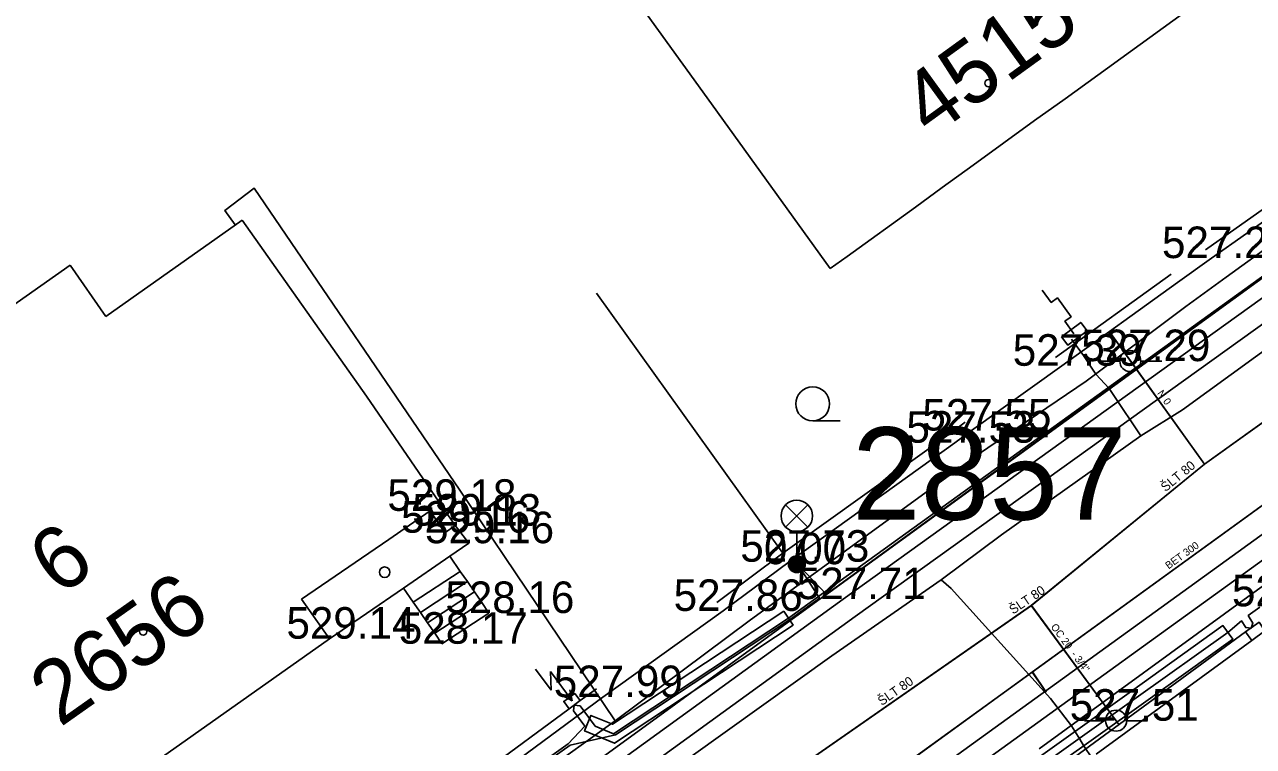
# Model space of a CAD drawing. Extents: x -668867 to -667827, y -1131943 to -1131019.
# Drawn here: x -668691.62 to -668662.4, y -1131354.94 to -1131337.78 of the extents above; entities that cross this region are included whole.
import ezdxf

# ---------------------------------------------------------------- set-up
doc = ezdxf.new("R2010")
doc.units = 0
for name, color, linetype in [('G_Bod_tecka', 7, 'Continuous'), ('G_Bod_vyska', 7, 'Continuous'), ('G_Budovy-znacky', 7, 'Continuous'), ('G_Budovy_Objekty', 7, 'Continuous'), ('G_Budovy_vstupy', 7, 'Continuous'), ('G_Cesty_Schody', 7, 'Continuous'), ('G_Cisla_orientacni', 7, 'Continuous'), ('G_Cisla_popisna', 7, 'Continuous'), ('G_Objekty_technicke', 7, 'Continuous'), ('G_Plochy_zpevnene', 7, 'Continuous'), ('G_Ploty', 7, 'Continuous'), ('G_Ploty_vstupy', 7, 'Continuous'), ('G_Site-Rozvadece', 7, 'Continuous'), ('G_Site-vodovod', 7, 'Continuous'), ('G_Z_CHRANICKA-TEPLOVOD_kotovane', 7, 'Continuous'), ('G_Z_ELsilove_podz_kotovane', 7, 'Continuous'), ('G_Z_KANAL_podz_kotovane', 7, 'Continuous'), ('G_Z_PLYNY_podz_geodeticky', 7, 'Continuous'), ('G_Z_SPOJE_podz_geodeticky', 7, 'Continuous'), ('G_Z_SPOJE_podz_kotovane', 7, 'Continuous'), ('G_Z_SPOJE_podz_priblizne', 7, 'Continuous'), ('G_Z_VODA_podz_kotovane', 7, 'Continuous'), ('G_Zelen-Znacky', 7, 'Continuous'), ('Vrstva 1', 7, 'Continuous'), ('Vrstva 10', 7, 'Continuous'), ('Vrstva 13', 7, 'Continuous'), ('Vrstva 17', 7, 'Continuous'), ('Vrstva 26', 7, 'Continuous'), ('Vrstva 3', 7, 'Continuous'), ('Vrstva 4', 7, 'Continuous'), ('Vrstva 6', 7, 'Continuous')]:
    doc.layers.add(name, color=color, linetype=linetype)

msp = doc.modelspace()

# ---------------------------------------------------------------- linework, layer by layer
at = {"layer": 'G_Bod_tecka'}
for p, q in [((-668663.4, -1131343.33), (-668663.4, -1131343.33)), ((-668666.96, -1131345.89), (-668666.96, -1131345.89)), ((-668665.33, -1131345.78), (-668665.33, -1131345.78)), ((-668669.11, -1131347.43), (-668669.11, -1131347.43)), ((-668669.5, -1131347.72), (-668669.5, -1131347.72)), ((-668681.98, -1131349.34), (-668681.98, -1131349.34)), ((-668681.38, -1131349.69), (-668681.38, -1131349.69)), ((-668681.63, -1131349.86), (-668681.63, -1131349.86)), ((-668681.06, -1131350.11), (-668681.06, -1131350.11)), ((-668673.44, -1131350.55), (-668673.44, -1131350.55)), ((-668673.26, -1131350.61), (-668673.26, -1131350.61)), ((-668672.16, -1131351.44), (-668672.16, -1131351.44)), ((-668680.58, -1131351.77), (-668680.58, -1131351.77)), ((-668675.01, -1131351.72), (-668675.01, -1131351.72)), ((-668684.37, -1131352.38), (-668684.37, -1131352.38)), ((-668681.7, -1131352.5), (-668681.7, -1131352.5)), ((-668677.87, -1131353.77), (-668677.87, -1131353.77)), ((-668665.67, -1131354.33), (-668665.67, -1131354.33))]:
    msp.add_line(p, q, dxfattribs=at)
at = {"layer": 'G_Budovy-znacky'}
for centre, radius in [((-668668.7, -1131339.17), 0.0875), ((-668683.06, -1131350.8), 0.125), ((-668688.8, -1131352.21), 0.0875)]:
    msp.add_circle(centre, radius, dxfattribs=at)
at = {"layer": 'G_Budovy_Objekty'}
for p, q in [((-668675.39, -1131339.52), (-668678.46, -1131335.27)), ((-668666.88, -1131339.54), (-668663.54, -1131337.12)), ((-668675.39, -1131339.52), (-668672.47, -1131343.58)), ((-668669.07, -1131341.12), (-668667.61, -1131340.06)), ((-668670.44, -1131342.12), (-668669.8, -1131341.65)), ((-668689.69, -1131344.72), (-668686.45, -1131342.43)), ((-668683.49, -1131346.61), (-668686.45, -1131342.43)), ((-668672.47, -1131343.58), (-668672.06, -1131343.29)), ((-668692.92, -1131345.17), (-668690.54, -1131343.5)), ((-668690.54, -1131343.5), (-668689.69, -1131344.72)), ((-668683.49, -1131346.61), (-668681.38, -1131349.69)), ((-668681.63, -1131349.86), (-668681.98, -1131349.34)), ((-668681.38, -1131349.69), (-668681.63, -1131349.86)), ((-668681.06, -1131350.11), (-668681.38, -1131349.69)), ((-668682.96, -1131350.02), (-668685.04, -1131351.44)), ((-668681.51, -1131350.42), (-668681.06, -1131350.11)), ((-668682.61, -1131351.18), (-668681.51, -1131350.42)), ((-668684.37, -1131352.38), (-668682.61, -1131351.18)), ((-668685.04, -1131351.44), (-668684.37, -1131352.38)), ((-668692.65, -1131358.23), (-668684.37, -1131352.38))]:
    msp.add_line(p, q, dxfattribs=at)
at = {"layer": 'G_Budovy_vstupy'}
msp.add_line((-668682.96, -1131350.02), (-668681.98, -1131349.34), dxfattribs=at)
msp.add_lwpolyline([(-668672.06, -1131343.29), (-668670.44, -1131342.12)], dxfattribs=at)
at = {"layer": 'G_Cesty_Schody'}
for p, q in [((-668646.06, -1131338.24), (-668670.62, -1131355.99)), ((-668655.32, -1131339.96), (-668671.87, -1131351.85)), ((-668681.26, -1131350.78), (-668681.51, -1131350.42)), ((-668682.38, -1131351.51), (-668681.26, -1131350.78)), ((-668681.09, -1131351.02), (-668681.26, -1131350.78)), ((-668682.38, -1131351.51), (-668682.61, -1131351.18)), ((-668682.21, -1131351.76), (-668681.09, -1131351.02)), ((-668682.04, -1131352), (-668680.92, -1131351.27)), ((-668680.92, -1131351.27), (-668681.09, -1131351.02)), ((-668680.75, -1131351.52), (-668680.92, -1131351.27)), ((-668682.21, -1131351.76), (-668682.38, -1131351.51)), ((-668681.87, -1131352.25), (-668680.75, -1131351.52)), ((-668680.58, -1131351.77), (-668680.75, -1131351.52)), ((-668671.87, -1131351.85), (-668715.28, -1131383.29)), ((-668682.04, -1131352), (-668682.21, -1131351.76)), ((-668681.7, -1131352.5), (-668680.58, -1131351.77)), ((-668681.87, -1131352.25), (-668682.04, -1131352)), ((-668681.7, -1131352.5), (-668681.87, -1131352.25))]:
    msp.add_line(p, q, dxfattribs=at)
at = {"layer": 'G_Objekty_technicke'}
for p, q in [((-668673.525, -1131349.195), (-668672.995, -1131349.725)), ((-668673.525, -1131349.725), (-668672.995, -1131349.195)), ((-668673.26, -1131350.61), (-668673.26, -1131349.835))]:
    msp.add_line(p, q, dxfattribs=at)
for centre, radius in [((-668673.26, -1131349.46), 0.375), ((-668673.26, -1131350.61), 0.2), ((-668673.26, -1131350.61), 0.18), ((-668673.26, -1131350.61), 0.16), ((-668673.26, -1131350.61), 0.14), ((-668673.26, -1131350.61), 0.12), ((-668673.26, -1131350.61), 0.1), ((-668673.26, -1131350.61), 0.08), ((-668673.26, -1131350.61), 0.06), ((-668673.26, -1131350.61), 0.04), ((-668673.26, -1131350.61), 0.02)]:
    msp.add_circle(centre, radius, dxfattribs=at)
at = {"layer": 'G_Plochy_zpevnene'}
for p, q in [((-668645.76, -1131338.64), (-668670.33, -1131356.39)), ((-668655.68, -1131339.6), (-668672.16, -1131351.44)), ((-668672.16, -1131351.44), (-668715.57, -1131382.88))]:
    msp.add_line(p, q, dxfattribs=at)
at = {"layer": 'G_Ploty'}
for p, q in [((-668659.96, -1131340.6), (-668663.54, -1131343.13)), ((-668659.82, -1131340.8), (-668663.4, -1131343.33)), ((-668664.36, -1131343.71), (-668667.11, -1131345.69)), ((-668666.96, -1131345.89), (-668664.21, -1131343.91)), ((-668678.02, -1131344.16), (-668673.59, -1131350.35)), ((-668669.64, -1131347.52), (-668669.26, -1131347.23)), ((-668669.5, -1131347.72), (-668669.11, -1131347.43)), ((-668669.64, -1131347.52), (-668673.59, -1131350.35)), ((-668673.44, -1131350.55), (-668669.5, -1131347.72)), ((-668673.59, -1131350.35), (-668675.16, -1131351.52)), ((-668675.01, -1131351.72), (-668673.44, -1131350.55)), ((-668672.43, -1131359.42), (-668662.59, -1131352.22)), ((-668666.14, -1131355.13), (-668662.44, -1131352.42)), ((-668678.02, -1131353.57), (-668678.41, -1131353.85)), ((-668677.87, -1131353.77), (-668680.54, -1131355.74)), ((-668678.67, -1131354.05), (-668680.69, -1131355.54))]:
    msp.add_line(p, q, dxfattribs=at)
at = {"layer": 'G_Ploty_vstupy'}
for p, q in [((-668664.21, -1131343.91), (-668663.4, -1131343.33)), ((-668669.11, -1131347.43), (-668666.96, -1131345.89)), ((-668677.87, -1131353.77), (-668675.01, -1131351.72))]:
    msp.add_line(p, q, dxfattribs=at)
for points in [[(-668667.61, -1131340.06), (-668666.88, -1131339.54)], [(-668669.8, -1131341.65), (-668669.07, -1131341.12)]]:
    msp.add_lwpolyline(points, dxfattribs=at)
at = {"layer": 'G_Site-Rozvadece'}
for p, q in [((-668679.47, -1131353.103), (-668679.098, -1131353.607)), ((-668679.098, -1131353.607), (-668679.12, -1131353.157)), ((-668679.12, -1131353.157), (-668678.6, -1131353.86)), ((-668678.6, -1131353.86), (-668678.657, -1131353.598)), ((-668678.834, -1131353.729), (-668678.6, -1131353.86))]:
    msp.add_line(p, q, dxfattribs=at)
for points in [[(-668666.67, -1131345.13), (-668666.886, -1131344.832), (-668666.738, -1131344.724), (-668667.063, -1131344.278), (-668667.211, -1131344.385), (-668667.429, -1131344.089)], [(-668666.97, -1131345.2), (-668666.51, -1131344.86), (-668666.36, -1131345.06), (-668666.82, -1131345.4), (-668666.97, -1131345.2)]]:
    msp.add_lwpolyline(points, dxfattribs=at)
for points in [[(-668662.59, -1131352.22), (-668662.44, -1131352.42), (-668662.13, -1131352.19), (-668662.27, -1131351.99)], [(-668678.67, -1131354.05), (-668678.41, -1131353.85), (-668678.54, -1131353.68), (-668678.8, -1131353.87)]]:
    msp.add_lwpolyline(points, close=True, dxfattribs=at)
at = {"layer": 'G_Site-vodovod'}
for p, q in [((-668665.58, -1131345.78), (-668666.08, -1131345.78)), ((-668665.08, -1131345.78), (-668664.58, -1131345.78)), ((-668665.92, -1131354.33), (-668666.42, -1131354.33)), ((-668665.42, -1131354.33), (-668664.92, -1131354.33))]:
    msp.add_line(p, q, dxfattribs=at)
for centre in [(-668665.33, -1131345.78), (-668665.67, -1131354.33)]:
    msp.add_circle(centre, 0.25, dxfattribs=at)
at = {"layer": 'G_Z_CHRANICKA-TEPLOVOD_kotovane'}
for points in [[(-668673.57, -1131351.723), (-668673.35, -1131352.056), (-668677.598, -1131354.865), (-668678.306, -1131354.575), (-668678.154, -1131354.205), (-668677.642, -1131354.415)], [(-668665.306, -1131353.627), (-668663.127, -1131352.068), (-668662.894, -1131352.393), (-668665.073, -1131353.952), (-668673.083, -1131359.672), (-668679.091, -1131364.101), (-668679.329, -1131363.779), (-668673.317, -1131359.348)]]:
    msp.add_lwpolyline(points, close=True, dxfattribs=at)
at = {"layer": 'G_Z_ELsilove_podz_kotovane'}
for points in [[(-668693.32, -1131365.32), (-668678.7, -1131354.88), (-668678.3, -1131354.463), (-668678.573, -1131354.097), (-668678.55, -1131353.96), (-668678.413, -1131353.977), (-668678.051, -1131354.463), (-668677.62, -1131354.64), (-668673.46, -1131351.89), (-668672.77, -1131351.39), (-668655.77, -1131339.14), (-668647.211, -1131332.84), (-668647.425, -1131332.469), (-668647.816, -1131332.199), (-668647.989, -1131331.886), (-668647.95, -1131331.75)], [(-668693.28, -1131365.28), (-668678.65, -1131354.91), (-668677.57, -1131354.67), (-668673.41, -1131351.92), (-668672.72, -1131351.42), (-668673.15, -1131350.75), (-668673.21, -1131350.64), (-668672.55, -1131351.33), (-668655.79, -1131339.15)], [(-668662.25, -1131351.63), (-668662.528, -1131351.831), (-668662.417, -1131352.009), (-668662.46, -1131352.13), (-668662.587, -1131352.115), (-668662.687, -1131351.955), (-668663.01, -1131352.23), (-668665.19, -1131353.79), (-668673.2, -1131359.51), (-668679.129, -1131363.881), (-668678.987, -1131364.06), (-668679.02, -1131364.18), (-668679.143, -1131364.184), (-668679.291, -1131363.997), (-668684.12, -1131367.41), (-668688.53, -1131370.65), (-668693.68, -1131374.48)]]:
    msp.add_lwpolyline(points, dxfattribs=at)
at = {"layer": 'G_Z_KANAL_podz_kotovane'}
msp.add_line((-668667.66, -1131353.17), (-668667.33, -1131353.65), dxfattribs=at)
msp.add_lwpolyline([(-668676.97, -1131359.91), (-668673.16, -1131357.16), (-668667.66, -1131353.17), (-668657.16, -1131345.57), (-668650.96, -1131341.08), (-668646.74, -1131338.02)], dxfattribs=at)
at = {"layer": 'G_Z_PLYNY_podz_geodeticky'}
for points in [[(-668693.74, -1131368.27), (-668688.53, -1131364.56), (-668685.86, -1131362.68), (-668683.64, -1131361.03), (-668682.73, -1131360.36), (-668681.55, -1131359.44), (-668678.31, -1131357), (-668672.43, -1131352.79), (-668669.83, -1131350.98), (-668668.39, -1131349.91), (-668665.08, -1131347.56), (-668664.09, -1131346.94), (-668657.64, -1131342.25)], [(-668665.08, -1131347.56), (-668665.74, -1131346.57), (-668665.83, -1131346.43), (-668666.15, -1131346.09), (-668666.44, -1131345.65), (-668666.73, -1131345.26)], [(-668669.83, -1131350.98), (-668669.59, -1131351.19), (-668667.23, -1131353.8), (-668666.73, -1131354.45), (-668666.53, -1131354.77), (-668666.44, -1131354.92), (-668666.23, -1131355.24)]]:
    msp.add_lwpolyline(points, dxfattribs=at)
at = {"layer": 'G_Z_SPOJE_podz_geodeticky'}
for points in [[(-668724.8, -1131389.05), (-668722.52, -1131387.56), (-668714.6, -1131381.91), (-668651.44, -1131335.95), (-668640.91, -1131328.07), (-668629.3, -1131319.46)], [(-668667.5, -1131355), (-668662.45, -1131351.32), (-668657.36, -1131347.66), (-668644.63, -1131338.47), (-668641.8, -1131336.42), (-668638.24, -1131333.8), (-668636.74, -1131332.77), (-668632.68, -1131329.88)], [(-668659.41, -1131341.15), (-668663.05, -1131343.78), (-668664.01, -1131344.48), (-668666.38, -1131346.26), (-668668.94, -1131347.99), (-668674.36, -1131351.93), (-668677.58, -1131354.33)], [(-668686.61, -1131342.54), (-668686.86, -1131342.2), (-668686.16, -1131341.67), (-668681.27, -1131348.85), (-668677.58, -1131354.33)], [(-668677.58, -1131354.33), (-668679.39, -1131355.63), (-668679.79, -1131356.31), (-668681.43, -1131357.56), (-668693.62, -1131366.49), (-668697.19, -1131368.91)]]:
    msp.add_lwpolyline(points, dxfattribs=at)
at = {"layer": 'G_Z_SPOJE_podz_kotovane'}
for points in [[(-668667.5, -1131355), (-668662.45, -1131351.32), (-668657.36, -1131347.66), (-668644.63, -1131338.47), (-668641.8, -1131336.42), (-668638.24, -1131333.8), (-668636.74, -1131332.77), (-668632.68, -1131329.88)], [(-668686.61, -1131342.54), (-668686.86, -1131342.2), (-668686.16, -1131341.67), (-668681.27, -1131348.85), (-668677.58, -1131354.33)]]:
    msp.add_lwpolyline(points, dxfattribs=at)
at = {"layer": 'G_Z_SPOJE_podz_priblizne'}
for points in [[(-668724.8, -1131389.05), (-668722.52, -1131387.56), (-668714.6, -1131381.91), (-668651.44, -1131335.95), (-668640.91, -1131328.07), (-668629.3, -1131319.46)], [(-668667.5, -1131355), (-668662.45, -1131351.32), (-668657.36, -1131347.66), (-668644.63, -1131338.47), (-668641.8, -1131336.42), (-668638.24, -1131333.8), (-668636.74, -1131332.77), (-668632.68, -1131329.88)], [(-668686.61, -1131342.54), (-668686.86, -1131342.2), (-668686.16, -1131341.67), (-668681.27, -1131348.85), (-668677.58, -1131354.33)]]:
    msp.add_lwpolyline(points, dxfattribs=at)
at = {"layer": 'G_Z_VODA_podz_kotovane'}
for points in [[(-668612.84, -1131311.89), (-668613.52, -1131312.39), (-668639.15, -1131330.75), (-668643.74, -1131334.04), (-668659.28, -1131345.16), (-668663.57, -1131348.23), (-668667.68, -1131351.59), (-668680.32, -1131360.39), (-668682.77, -1131361.98), (-668694.38, -1131370.3), (-668700.33, -1131374.56), (-668716.2, -1131385.93), (-668719.87, -1131388.55), (-668728.66, -1131395.15), (-668734.59, -1131399.59), (-668743.8, -1131406.5), (-668743.96, -1131406.62), (-668747.09, -1131408.97), (-668758.727, -1131416.908)], [(-668663.57, -1131348.23), (-668665.3, -1131345.81), (-668665.83, -1131345.07)], [(-668667.68, -1131351.59), (-668665.67, -1131354.33), (-668665.6, -1131354.42)]]:
    msp.add_lwpolyline(points, dxfattribs=at)
at = {"layer": 'G_Zelen-Znacky'}
msp.add_line((-668672.882, -1131347.2), (-668672.232, -1131347.197), dxfattribs=at)
msp.add_circle((-668672.882, -1131346.797), 0.403, dxfattribs=at)
at = {"layer": 'Vrstva 1'}
msp.add_line((-668673.15, -1131350.75), (-668673.15, -1131350.75), dxfattribs=at)
at = {"layer": 'Vrstva 10'}
msp.add_lwpolyline([(-668676.971, -1131359.914), (-668673.164, -1131357.156), (-668667.665, -1131353.173), (-668657.161, -1131345.565), (-668650.963, -1131341.076), (-668646.74, -1131338.017)], dxfattribs=at)
at = {"layer": 'Vrstva 13'}
msp.add_line((-668667.665, -1131353.173), (-668667.332, -1131353.653), dxfattribs=at)
at = {"layer": 'Vrstva 17'}
for p, q in [((-668672.55, -1131351.33), (-668655.79, -1131339.15)), ((-668673.15, -1131350.75), (-668673.21, -1131350.64)), ((-668673.21, -1131350.64), (-668672.55, -1131351.33)), ((-668672.72, -1131351.42), (-668673.15, -1131350.75)), ((-668673.41, -1131351.92), (-668672.72, -1131351.42)), ((-668677.57, -1131354.67), (-668673.41, -1131351.92)), ((-668678.65, -1131354.91), (-668677.57, -1131354.67)), ((-668693.28, -1131365.28), (-668678.65, -1131354.91))]:
    msp.add_line(p, q, dxfattribs=at)
at = {"layer": 'Vrstva 26'}
for points in [[(-668612.843, -1131311.885), (-668613.516, -1131312.393), (-668639.148, -1131330.746), (-668643.745, -1131334.037), (-668659.276, -1131345.158), (-668663.568, -1131348.231), (-668667.684, -1131351.593), (-668680.32, -1131360.39), (-668682.771, -1131361.982), (-668694.383, -1131370.3), (-668700.33, -1131374.561), (-668716.198, -1131385.926), (-668719.869, -1131388.555), (-668728.661, -1131395.148), (-668734.589, -1131399.593), (-668743.804, -1131406.503), (-668743.957, -1131406.618), (-668747.094, -1131408.971), (-668758.727, -1131416.908)], [(-668663.568, -1131348.231), (-668665.304, -1131345.807), (-668665.831, -1131345.075)], [(-668667.684, -1131351.593), (-668665.667, -1131354.33), (-668665.597, -1131354.425)]]:
    msp.add_lwpolyline(points, dxfattribs=at)
at = {"layer": 'Vrstva 6'}
for p, q in [((-668665.304, -1131345.807), (-668665.304, -1131345.807)), ((-668665.667, -1131354.33), (-668665.667, -1131354.33))]:
    msp.add_line(p, q, dxfattribs=at)

# ---------------------------------------------------------------- texts
at = {"layer": 'G_Bod_vyska'}
for s, p in [('527.26', (-668664.578, -1131343.33)), ('527.39', (-668668.126, -1131345.89)), ('527.29', (-668666.496, -1131345.78)), ('527.55', (-668670.274, -1131347.43)), ('527.53', (-668670.654, -1131347.72)), ('529.18', (-668682.994, -1131349.34)), ('529.13', (-668682.404, -1131349.69)), ('529.16', (-668682.668, -1131349.86)), ('529.16', (-668682.098, -1131350.11)), ('527.73', (-668674.604, -1131350.55)), ('0.00', (-668674.04, -1131350.61)), ('527.71', (-668673.262, -1131351.44)), ('527.86', (-668676.188, -1131351.72)), ('527.42', (-668662.914, -1131351.61)), ('528.16', (-668681.616, -1131351.77)), ('529.14', (-668685.394, -1131352.38)), ('528.17', (-668682.722, -1131352.5)), ('527.99', (-668679.038, -1131353.77)), ('527.51', (-668666.772, -1131354.33))]:
    msp.add_text(s, height=0.75, dxfattribs=at).set_placement(p)
at = {"layer": 'G_Cisla_orientacni'}
msp.add_text('6', height=1.5, rotation=36.2212, dxfattribs=at).set_placement((-668690.786, -1131351.392))
at = {"layer": 'G_Cisla_popisna'}
for s, rotation, p in [('4515', 35.9246, (-668670.066, -1131340.49)), ('2656', 35.207, (-668690.778, -1131354.5))]:
    msp.add_text(s, height=1.5, rotation=rotation, dxfattribs=at).set_placement(p)
at = {"layer": 'Vrstva 3'}
msp.add_text('BET 300', height=0.1755, rotation=35.8807, dxfattribs=at).set_placement((-668664.42, -1131350.735))
at = {"layer": 'Vrstva 4'}
for s, height, rotation, p in [('N 0', 0.1755, 305.6575, (-668664.7, -1131346.546)), ('ŠLT 80', 0.2194, 39.2356, (-668664.496, -1131348.898)), ('ŠLT 80', 0.2194, 33.8657, (-668668.117, -1131351.809)), ('OC 20  - 3/4"', 0.17551, 306.3029, (-668667.231, -1131352.1)), ('ŠLT 80', 0.2194, 34.8779, (-668671.24, -1131353.983))]:
    msp.add_text(s, height=height, rotation=rotation, dxfattribs=at).set_placement(p)
msp.add_text('2857', height=2.1939, dxfattribs=at).set_placement((-668671.946, -1131349.549))

doc.saveas('drawing.dxf')
